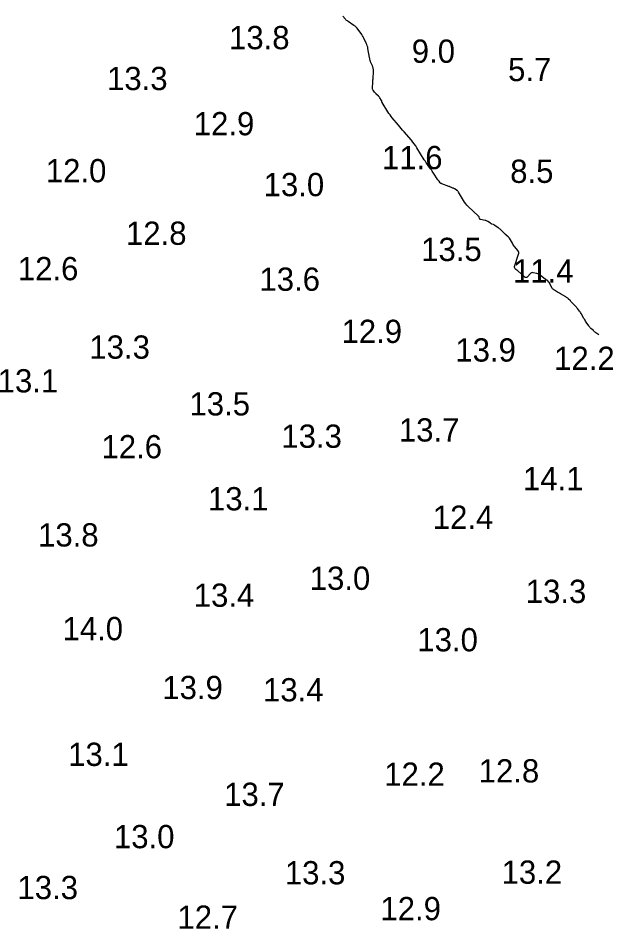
# Model space of a CAD drawing. Extents: x 815352 to 820877, y 582403 to 597439.
# Drawn here: x 818278.3 to 818403.1, y 595119.3 to 595315.1 of the extents above; entities that cross this region are included whole.
import ezdxf

# ---------------------------------------------------------------- set-up
doc = ezdxf.new("R2010")
doc.units = 0
doc.layers.add('V-CONT-EL12', color=7, linetype='Continuous')
doc.layers.add('V-TOPO-SOUN', color=7, linetype='Continuous')

msp = doc.modelspace()

# ---------------------------------------------------------------- linework, layer by layer
at = {"layer": 'V-CONT-EL12'}
msp.add_lwpolyline([(818403.1, 595247.02), (818402.46, 595247.45), (818402.31, 595247.56), (818402.17, 595247.67), (818402.03, 595247.78), (818401.89, 595247.9), (818401.36, 595248.39), (818401.23, 595248.51), (818401.11, 595248.64), (818401, 595248.78), (818400.9, 595248.93), (818400.34, 595249.76), (818400.22, 595249.95), (818400.1, 595250.14), (818399.99, 595250.34), (818399.87, 595250.54), (818399.36, 595251.46), (818399.26, 595251.62), (818399.16, 595251.78), (818399.06, 595251.94), (818398.94, 595252.09), (818398.49, 595252.69), (818398.37, 595252.84), (818398.25, 595252.98), (818398.12, 595253.12), (818397.99, 595253.26), (818397.41, 595253.84), (818397.3, 595253.95), (818397.19, 595254.06), (818397.07, 595254.18), (818396.96, 595254.29), (818396.51, 595254.75), (818396.4, 595254.86), (818396.28, 595254.97), (818396.15, 595255.06), (818396.01, 595255.14), (818394.81, 595255.85), (818394.65, 595255.94), (818394.49, 595256.03), (818394.33, 595256.12), (818394.17, 595256.21), (818393.53, 595256.57), (818393.38, 595256.67), (818393.25, 595256.79), (818393.14, 595256.92), (818393.04, 595257.07), (818392.48, 595258.14), (818392.44, 595258.2), (818392.4, 595258.26), (818392.36, 595258.31), (818392.32, 595258.36), (818392.1, 595258.59), (818392.07, 595258.63), (818392.03, 595258.66), (818391.99, 595258.69), (818391.94, 595258.72), (818391.77, 595258.82), (818391.72, 595258.84), (818391.68, 595258.87), (818391.64, 595258.9), (818391.6, 595258.93), (818390.46, 595259.85), (818390.3, 595259.96), (818390.13, 595260.06), (818389.96, 595260.13), (818389.77, 595260.18), (818388.99, 595260.35), (818388.8, 595260.37), (818388.63, 595260.34), (818388.47, 595260.26), (818388.33, 595260.14), (818387.72, 595259.48), (818387.57, 595259.36), (818387.42, 595259.31), (818387.26, 595259.34), (818387.1, 595259.45), (818385.64, 595260.77), (818385.59, 595260.81), (818385.55, 595260.85), (818385.5, 595260.89), (818385.45, 595260.92), (818385.25, 595261.05), (818385.2, 595261.09), (818385.16, 595261.13), (818385.12, 595261.17), (818385.09, 595261.22), (818384.95, 595261.47), (818384.93, 595261.53), (818384.91, 595261.59), (818384.91, 595261.66), (818384.93, 595261.72), (818385.83, 595264.31), (818385.88, 595264.53), (818385.87, 595264.75), (818385.8, 595264.95), (818385.68, 595265.14), (818385.05, 595265.9), (818384.9, 595266.09), (818384.76, 595266.28), (818384.62, 595266.48), (818384.49, 595266.69), (818383.85, 595267.78), (818383.79, 595267.86), (818383.73, 595267.94), (818383.67, 595268.01), (818383.6, 595268.07), (818383.18, 595268.41), (818383.16, 595268.43), (818383.14, 595268.45), (818383.12, 595268.47), (818383.1, 595268.49), (818383.03, 595268.57), (818383.01, 595268.59), (818382.99, 595268.61), (818382.97, 595268.63), (818382.95, 595268.65), (818381.98, 595269.58), (818381.85, 595269.7), (818381.71, 595269.81), (818381.57, 595269.92), (818381.43, 595270.03), (818380.69, 595270.54), (818380.62, 595270.58), (818380.55, 595270.63), (818380.48, 595270.66), (818380.4, 595270.7), (818380.08, 595270.82), (818380.01, 595270.86), (818379.93, 595270.89), (818379.86, 595270.93), (818379.79, 595270.98), (818379.18, 595271.38), (818379.05, 595271.46), (818378.92, 595271.52), (818378.78, 595271.57), (818378.64, 595271.6), (818377.65, 595271.8), (818377.58, 595271.83), (818377.52, 595271.86), (818377.48, 595271.92), (818377.45, 595271.98), (818377.35, 595272.28), (818377.32, 595272.35), (818377.28, 595272.41), (818377.24, 595272.47), (818377.19, 595272.53), (818374.99, 595274.62), (818374.71, 595274.9), (818374.45, 595275.2), (818374.22, 595275.52), (818374, 595275.86), (818372.91, 595277.71), (818372.84, 595277.82), (818372.76, 595277.91), (818372.67, 595278), (818372.57, 595278.07), (818372.12, 595278.36), (818372.03, 595278.42), (818371.92, 595278.47), (818371.82, 595278.53), (818371.71, 595278.57), (818371.28, 595278.74), (818371.17, 595278.78), (818371.07, 595278.83), (818370.96, 595278.87), (818370.85, 595278.91), (818369.32, 595279.47), (818369.23, 595279.51), (818369.14, 595279.56), (818369.07, 595279.62), (818369, 595279.7), (818368.73, 595280.01), (818368.66, 595280.09), (818368.6, 595280.17), (818368.54, 595280.25), (818368.48, 595280.33), (818367.54, 595281.77), (818367.39, 595282), (818367.24, 595282.22), (818367.08, 595282.45), (818366.92, 595282.67), (818366.05, 595283.88), (818366.01, 595283.93), (818365.97, 595283.99), (818365.93, 595284.05), (818365.9, 595284.11), (818365.71, 595284.43), (818365.69, 595284.45), (818365.68, 595284.46), (818365.67, 595284.48), (818365.65, 595284.49), (818365.59, 595284.55), (818365.58, 595284.56), (818365.57, 595284.57), (818365.55, 595284.59), (818365.54, 595284.61), (818363.98, 595287.2), (818363.71, 595287.63), (818363.41, 595288.04), (818363.11, 595288.45), (818362.78, 595288.84), (818361.21, 595290.64), (818360.9, 595290.99), (818360.59, 595291.35), (818360.29, 595291.72), (818359.98, 595292.08), (818358.68, 595293.65), (818358.43, 595293.96), (818358.19, 595294.29), (818357.96, 595294.62), (818357.74, 595294.95), (818356.5, 595296.93), (818356.47, 595296.96), (818356.46, 595297), (818356.44, 595297.04), (818356.43, 595297.09), (818356.4, 595297.26), (818356.39, 595297.3), (818356.38, 595297.35), (818356.36, 595297.39), (818356.34, 595297.42), (818356.01, 595297.98), (818355.94, 595298.08), (818355.87, 595298.18), (818355.79, 595298.27), (818355.7, 595298.35), (818355.16, 595298.85), (818355.07, 595298.93), (818354.99, 595299.02), (818354.91, 595299.11), (818354.84, 595299.2), (818354.55, 595299.6), (818354.49, 595299.7), (818354.45, 595299.81), (818354.43, 595299.92), (818354.42, 595300.04), (818354.48, 595301.36), (818354.5, 595301.6), (818354.51, 595301.83), (818354.53, 595302.06), (818354.55, 595302.29), (818354.65, 595303.44), (818354.66, 595303.56), (818354.65, 595303.68), (818354.65, 595303.81), (818354.63, 595303.93), (818354.55, 595304.41), (818354.52, 595304.53), (818354.49, 595304.64), (818354.45, 595304.76), (818354.4, 595304.87), (818354.02, 595305.68), (818353.99, 595305.75), (818353.96, 595305.83), (818353.94, 595305.9), (818353.92, 595305.98), (818353.85, 595306.29), (818353.83, 595306.37), (818353.81, 595306.45), (818353.8, 595306.53), (818353.78, 595306.61), (818353.44, 595308.54), (818353.38, 595308.83), (818353.3, 595309.12), (818353.2, 595309.4), (818353.09, 595309.68), (818352.57, 595310.78), (818352.44, 595311.04), (818352.3, 595311.3), (818352.14, 595311.55), (818351.97, 595311.79), (818351.27, 595312.73), (818351.09, 595312.96), (818350.89, 595313.16), (818350.67, 595313.35), (818350.43, 595313.53), (818349.17, 595314.37), (818349.01, 595314.49), (818348.85, 595314.62), (818348.71, 595314.75), (818348.58, 595314.9), (818348.06, 595315.51)], dxfattribs=at)

# ---------------------------------------------------------------- texts
at = {"layer": 'V-TOPO-SOUN'}
for s, p in [('13.8 ', (818323.58, 595308.41)), ('9.0', (818362.86, 595305.49)), ('5.7', (818383.56, 595301.55)), ('13.3 ', (818297.36, 595299.62)), ('12.9 ', (818316, 595289.9)), ('11.6 ', (818356.46, 595282.62)), ('12.0 ', (818284.2, 595279.8)), ('8.5', (818384.02, 595279.67)), ('13.0 ', (818331.02, 595276.81)), ('12.8 ', (818301.43, 595266.35)), ('13.5 ', (818364.88, 595262.87)), ('12.6 ', (818278.18, 595258.74)), ('11.4 ', (818384.63, 595258.24)), ('13.6 ', (818330.12, 595256.47)), ('12.9 ', (818347.76, 595245.25)), ('13.3 ', (818293.56, 595241.87)), ('13.9 ', (818372.23, 595241.25)), ('12.2 ', (818393.46, 595239.45)), ('13.1 ', (818273.85, 595234.62)), ('13.5 ', (818315.08, 595229.67)), ('13.7 ', (818360.09, 595224.06)), ('13.3 ', (818334.83, 595222.71)), ('12.6 ', (818296.16, 595220.45)), ('14.1 ', (818386.77, 595213.59)), ('13.1 ', (818319.06, 595209.26)), ('12.4 ', (818367.38, 595205.29)), ('13.8 ', (818282.53, 595201.49)), ('13.0 ', (818340.93, 595192.17)), ('13.4 ', (818316, 595188.53)), ('13.3 ', (818387.36, 595189.35)), ('14.0 ', (818287.78, 595181.34)), ('13.0 ', (818364.06, 595178.95)), ('13.9 ', (818309.24, 595168.68)), ('13.4 ', (818330.89, 595168.19)), ('13.1 ', (818289, 595154.31)), ('12.8 ', (818377.25, 595150.76)), ('12.2 ', (818356.94, 595150.04)), ('13.7 ', (818322.53, 595145.71)), ('13.0 ', (818298.84, 595136.62)), ('13.2 ', (818382.17, 595128.98)), ('13.3 ', (818335.58, 595128.85)), ('13.3 ', (818278.1, 595125.67)), ('12.9 ', (818356.12, 595121.14)), ('12.7 ', (818312.49, 595119.3))]:
    msp.add_text(s, height=5, dxfattribs=at).set_placement(p)

doc.saveas('drawing.dxf')
